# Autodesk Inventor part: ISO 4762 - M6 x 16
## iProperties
Created: 2008-08
Part Number: ISO 4762 - M6 x 16
Material: BgAAAEgAAABOAEEATQBFAFMACgBNAGEAdABlAHIAaQBhAGwAcwAKADEAOgBTAHQAZQBlAGwALAAgAE0AaQBsAGQACgAKAEUATgBEAAoAAAA=
Description: Innensechskantschraube
Vendor: Autodesk Inc.
Document SubType Name: Modeling
Standard: ISO 4762
Designer: U.Rapp
Standards Organization: DIN
Language: de-DE
Size Designation: M6 x 16
Categories: <MemberInstance Version="R10.0.0"><Categories><Category DisplayName="Schrauben" InternalName="e4da775c-781d-43d5-af7c-5136215cf5a6" Mnemonic="FSTN"><Category Di
Author: U.Rapp
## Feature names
1. Körper [Revolution]
2. Loch [Extrusion]
3. Rundung1 [Fillet]
4. Fase1 [Chamfer]
